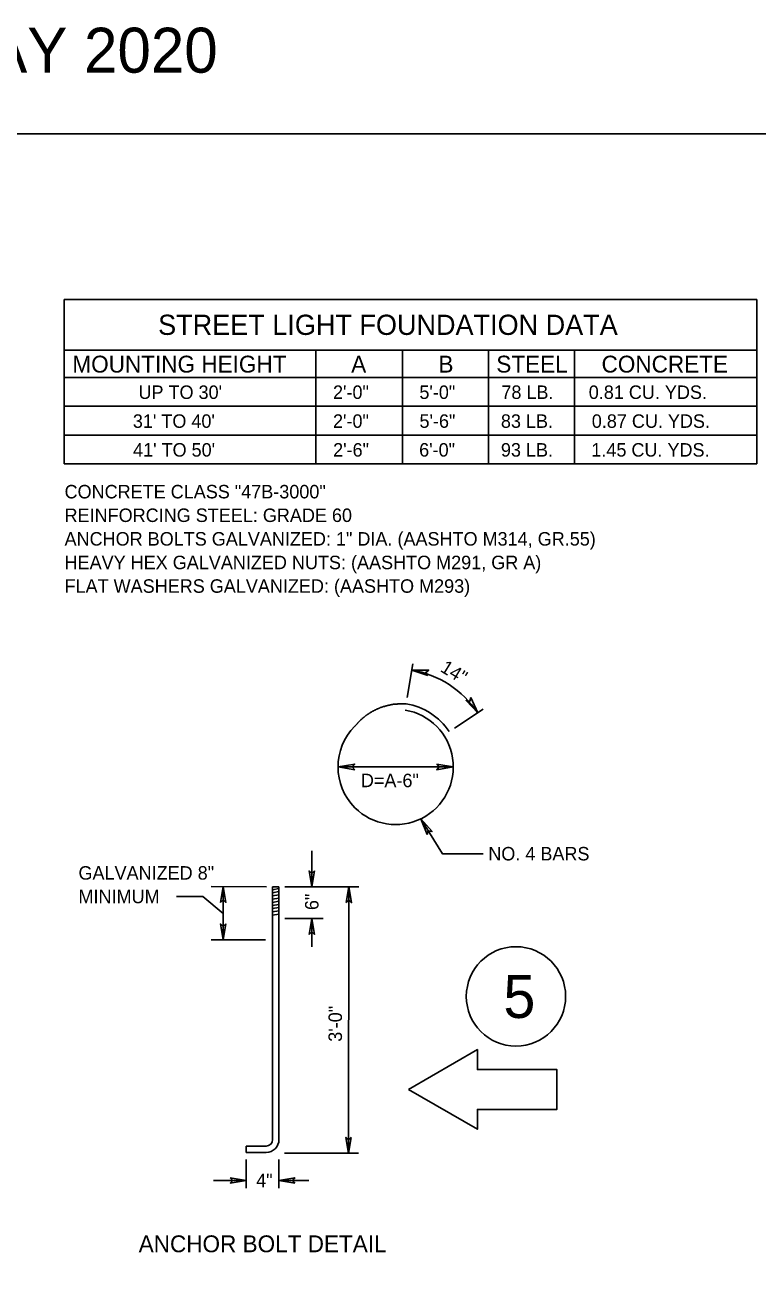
# Model space of a CAD drawing. Extents: x 99836 to 115004, y 99786 to 102182.
# Drawn here: x 106009 to 106661, y 101056 to 102182 of the extents above; entities that cross this region are included whole.
import ezdxf

# ---------------------------------------------------------------- set-up
doc = ezdxf.new("R2010")
doc.units = 0
for name, color, linetype in [('Border Line', 7, 'Continuous'), ('Border Organizer Shape', 7, 'Continuous'), ('Default', 7, 'Continuous'), ('Notes General Notes', 7, 'Continuous')]:
    doc.layers.add(name, color=color, linetype=linetype)

msp = doc.modelspace()

# ---------------------------------------------------------------- linework, layer by layer
at = {"layer": 'Border Organizer Shape'}
for p, q in [((106043.5, 101938.1), (106660.3, 101938.1)), ((106043.5, 101791.8), (106043.5, 101938.1)), ((106660.3, 101791.8), (106660.3, 101938.1)), ((106043.5, 101893.1), (106660.3, 101893.1)), ((106267.5, 101791.8), (106267.5, 101893.1)), ((106344.7, 101791.8), (106344.7, 101893.1)), ((106421.3, 101791.8), (106421.3, 101893.1)), ((106498, 101791.8), (106498, 101893.1)), ((106043.5, 101868.8), (106660.3, 101868.8)), ((106043.5, 101843.1), (106660.3, 101843.1)), ((106043.5, 101817.4), (106660.3, 101817.4)), ((106043.5, 101791.8), (106660.3, 101791.8)), ((106349, 101584), (106354, 101613.9)), ((106391.2, 101556.7), (106416.5, 101573.4)), ((106287.4, 101522.1), (106390, 101522.1)), ((106264, 101415.5), (106264, 101447.4)), ((106223.6, 101415.5), (106174.3, 101415.6)), ((106185.1, 101368.3), (106185.1, 101415.6)), ((106229.1, 101415.5), (106229.1, 101396.6)), ((106234.8, 101415.5), (106229.1, 101415.5)), ((106234.8, 101413.8), (106229.1, 101412.8)), ((106234.8, 101415.5), (106234.8, 101396.6)), ((106305.9, 101415.5), (106240, 101415.5)), ((106296.8, 101178.3), (106297, 101415.5)), ((106166.9, 101406.8), (106143.6, 101406.8)), ((106166.9, 101406.8), (106185.1, 101391.8)), ((106234.8, 101411.1), (106229.1, 101410.1)), ((106234.8, 101408.2), (106229.1, 101407.3)), ((106234.7, 101405.4), (106229.1, 101404.5)), ((106234.7, 101402.5), (106229.1, 101401.6)), ((106234.7, 101399.8), (106229, 101398.8)), ((106234.7, 101396.9), (106229.1, 101396)), ((106229.1, 101396.6), (106229.1, 101190.4)), ((106234.7, 101394.1), (106229.1, 101393.2)), ((106234.7, 101391.2), (106229.1, 101390.3)), ((106234.8, 101396.6), (106234.8, 101190.4)), ((106274.1, 101387.1), (106240, 101387.2)), ((106264, 101362.1), (106264, 101387.1)), ((106222.9, 101368.2), (106174.3, 101368.3)), ((106205.5, 101184.7), (106223.4, 101184.7)), ((106205.5, 101184.7), (106205.5, 101179)), ((106205.5, 101179), (106223.4, 101179)), ((106305.7, 101178.3), (106239.8, 101178.3)), ((106205.5, 101147.1), (106205.5, 101172.8)), ((106234.8, 101147.1), (106234.8, 101172.8)), ((106205.5, 101154.1), (106176.5, 101154.1)), ((106261.4, 101154.1), (106234.8, 101154.1))]:
    msp.add_line(p, q, dxfattribs=at)
for points in [[(106367.3, 101603.4), (106353.1, 101608.3), (106368.1, 101608.3), (106365.4, 101606.2)], [(106405.6, 101584), (106411.7, 101570.2), (106401.4, 101581.2), (106404.8, 101580.7)], [(106302.3, 101519.6), (106287.4, 101522.1), (106302.3, 101524.6), (106299.9, 101522.1)], [(106375.2, 101524.6), (106390, 101522.1), (106375.2, 101519.6), (106377.5, 101522.1)], [(106366.8, 101462), (106361.1, 101475.9), (106371.1, 101464.6), (106367.7, 101465.3)], [(106266.4, 101429.6), (106264, 101415.5), (106261.6, 101429.6), (106264, 101427.4)], [(106182.7, 101401.5), (106185.1, 101415.6), (106187.5, 101401.5), (106185.1, 101403.7)], [(106294.6, 101401.4), (106297, 101415.5), (106299.4, 101401.4), (106297, 101403.6)], [(106187.5, 101382.4), (106185.1, 101368.3), (106182.7, 101382.4), (106185.1, 101380.2)], [(106261.6, 101373), (106264, 101387.1), (106266.4, 101373), (106264, 101375.3)], [(106299.2, 101192.4), (106296.8, 101178.3), (106294.4, 101192.4), (106296.8, 101190.2)], [(106191.4, 101156.5), (106205.5, 101154.1), (106191.4, 101151.7), (106193.6, 101154.1)], [(106248.9, 101151.7), (106234.8, 101154.1), (106248.9, 101156.5), (106246.7, 101154.1)]]:
    msp.add_lwpolyline(points, close=True, dxfattribs=at)
msp.add_lwpolyline([(106361.1, 101475.9), (106380.3, 101444.9), (106416.7, 101444.9)], dxfattribs=at)
for centre, radius, start, end in [((106338.7, 101522.1), 87.4, 33.427, 80.5536), ((106338.7, 101522.1), 51.3, 224.9925, 80.5568), ((106338.7, 101522.1), 57, 33.4279, 80.5568), ((106338.7, 101522.1), 51.3, 134.9925, 224.9925), ((106223.4, 101190.4), 5.68, 270, 360), ((106223.4, 101190.4), 11.4, 270, 360)]:
    msp.add_arc(centre, radius, start, end, dxfattribs=at)
msp.add_spline([(106348.1, 101578.3), (106347.2, 101578.3), (106346.5, 101578.4), (106345.7, 101578.4), (106344.9, 101578.4), (106344.1, 101578.4), (106343.3, 101578.3), (106342.5, 101578.3), (106341.7, 101578.3), (106340.9, 101578.2), (106340.1, 101578.1), (106339.3, 101578.1), (106338.5, 101578.1), (106337.8, 101578), (106336.9, 101577.9), (106336.2, 101577.8), (106335.4, 101577.6), (106334.7, 101577.5), (106333.8, 101577.3), (106333, 101577.1), (106332.3, 101577), (106331.5, 101576.8), (106330.7, 101576.6), (106330, 101576.4), (106329.2, 101576.1), (106328.4, 101576), (106327.6, 101575.8), (106326.9, 101575.5), (106326.2, 101575.2), (106325.4, 101575), (106324.6, 101574.7), (106323.9, 101574.3), (106323.2, 101574), (106322.4, 101573.8), (106321.7, 101573.4), (106321, 101573), (106320.2, 101572.7), (106319.6, 101572.3), (106318.9, 101571.9), (106318.1, 101571.6), (106317.5, 101571.2), (106316.8, 101570.9), (106316, 101570.4), (106315.4, 101570), (106314.8, 101569.6), (106314.1, 101569.1), (106313.4, 101568.7), (106312.8, 101568.2), (106312.1, 101567.8), (106311.5, 101567.3), (106310.8, 101566.7), (106310.3, 101566.3), (106309.7, 101565.7), (106309, 101565.3), (106308.5, 101564.7), (106307.8, 101564.2), (106307.3, 101563.6), (106306.7, 101563.1), (106306.2, 101562.6), (106305.6, 101561.9), (106305, 101561.4), (106304.6, 101560.8), (106304, 101560.2), (106303.5, 101559.5), (106302.9, 101559), (106302.5, 101558.4)], degree=3, dxfattribs=at)
at = {"layer": 'Default'}
msp.add_lwpolyline([(105069.9, 102085.7), (108269.6, 102085.7), (108269.6, 99886.1), (105069.9, 99886.1)], close=True, dxfattribs=at)
at = {"layer": 'Notes General Notes'}
msp.add_lwpolyline([(106350, 101235.1), (106411.4, 101199.6), (106411.4, 101217.3), (106482.3, 101217.3), (106482.3, 101252.8), (106411.4, 101252.8), (106411.4, 101270.6)], close=True, dxfattribs=at)
msp.add_circle((106445.8, 101317.9), 44.2, dxfattribs=at)

# ---------------------------------------------------------------- texts
at = {"layer": 'Border Line'}
msp.add_text('Approved Date MAY 2020', height=40, dxfattribs=at).set_placement((105558.8, 102140))
at = {"layer": 'Border Organizer Shape'}
for s, height, p in [('STREET LIGHT FOUNDATION DATA', 18, (106127.2, 101906.6)), ('MOUNTING HEIGHT', 15, (106050.9, 101873.1)), ('A', 15, (106299.1, 101873.1)), ('B', 15, (106376.8, 101873.1)), ('STEEL', 15, (106428.3, 101873.1)), ('CONCRETE', 15, (106522, 101873.1)), ("UP TO 30'", 12, (106109.7, 101849.6)), ('2\'-0"', 12, (106282.9, 101849.6)), ('5\'-0"', 12, (106359.8, 101849.6)), ('78 LB.', 12, (106432.8, 101849.6)), ('0.81 CU. YDS.', 12, (106510.6, 101849.6)), ("31' TO 40'", 12, (106104.7, 101823.9)), ('2\'-0"', 12, (106282.9, 101823.9)), ('5\'-6"', 12, (106359.9, 101823.9)), ('83 LB.', 12, (106432.4, 101823.9)), ('0.87 CU. YDS.', 12, (106513.3, 101823.9)), ("41' TO 50'", 12, (106104.9, 101798.3)), ('2\'-6"', 12, (106283, 101798.3)), ('6\'-0"', 12, (106359.6, 101798.3)), ('93 LB.', 12, (106432.4, 101798.3)), ('1.45 CU. YDS.', 12, (106512.9, 101798.3)), ('CONCRETE CLASS "47B-3000"', 12, (106043.9, 101761.1)), ('REINFORCING STEEL: GRADE 60', 12, (106043.9, 101740.1)), ('ANCHOR BOLTS GALVANIZED: 1" DIA. (AASHTO M314, GR.55)', 12, (106043.9, 101719.1)), ('HEAVY HEX GALVANIZED NUTS: (AASHTO M291, GR A)', 12, (106043.9, 101698.1)), ('FLAT WASHERS GALVANIZED: (AASHTO M293)', 12, (106043.9, 101677.1)), ('GALVANIZED 8"', 12, (106056.3, 101421.8)), ('MINIMUM ', 12, (106056.3, 101400.8)), ('4"', 12, (106214.5, 101148.1)), ('ANCHOR BOLT DETAIL', 15, (106109.9, 101090.2))]:
    msp.add_text(s, height=height, dxfattribs=at).set_placement(p)
for s, rotation, p in [('14"', 328.8322, (106377.6, 101607.6)), ('D=A-6"', 359.9925, (106307.7, 101504.1)), (' NO. 4 BARS', 359.9925, (106416.7, 101438.9)), ('6"', 90, (106270, 101394.7)), ('3\'-0"', 90, (106290.9, 101277.5))]:
    msp.add_text(s, height=12, rotation=rotation, dxfattribs=at).set_placement(p)
at = {"layer": 'Notes General Notes'}
msp.add_text('5', height=38.3, dxfattribs=at).set_placement((106434.6, 101298.7))

doc.saveas('drawing.dxf')
